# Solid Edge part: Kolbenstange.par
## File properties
Username: bmolnar
Dokumentum tartalom típus: 0
Author: bmolnar
Last saved by: bmolnar
Revision: 83
Sűrűség: 0,000 kg/m^3
Pontosság: 0,990
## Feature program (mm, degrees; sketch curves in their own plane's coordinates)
base feature "unnamed BaseFeature 1"
sketch for "unnamed Protrusion 1" plane through (0, 0, -17.4) normal (0, 0, -1) x-axis (0, 1, 0)
  circle centre (0, 0) radius 20
extrude "unnamed Protrusion 1" add finite 17.45 along +normal
sketch for "Kihúzás_2" #1 plane through (0, 0, -17.4) normal (0, 0, -1) x-axis (0, 1, 0)
  circle centre (0, 0) radius 6
sketch for "Kihúzás_2" #2 plane through (0, 0, -17.4) normal (0, 0, -1) x-axis (0, 1, 0)
  circle centre (0, 0) radius 20
extrude "Kihúzás_2" add finite 12.55 along -normal
sketch for "Furat_1" plane through (0, 0, 49.9) normal (0, 0, 1) x-axis (0, -1, 0)
  hole centre (0, 0) bore radius 2.4585
hole "Furat_1" nominal diameter 6 finite  ThreadDepth = 12.5 mm; VBottomAngle = 118 deg
chamfer "Letörés_1" setback 0.5  SetBackValue2 = 45 deg
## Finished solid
Body 1: solid body, 17 faces, 23 edges, 8 vertices.
  Faces by surface: plane 7, cylinder 5, cone 3, torus 2
  Edges by curve: circle 13, line 6, curve on surface 2, ellipse 2
Bounding box of the edges (mm; curved faces can reach further): 40.000 x 40.000 x 87.250, from (-20, -20, -34.85) to (20, 20, 52.4).
Cylindrical faces by radius (mm): R2.4585 x2, R3.125 x1, R6 x1, R20 x1
Conical faces (half-angle, radius in mm at the cone's reference point): 45 deg R2.9585 x1, 45 deg R3.225 x1, 59 deg R2.4585 x1
Toroidal faces (ring radius, tube radius in mm): R2.925 r0.2 x1, R4.7 r1.3 x1
Planar faces by outward normal: +x 1, +z 2, -x 1, -z 1, oblique 2
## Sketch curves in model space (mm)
circle centre (0, 0, -17.4) radius 6
circle centre (0, 0, -17.4) radius 20
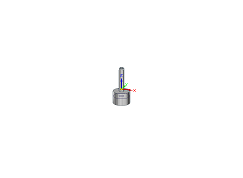
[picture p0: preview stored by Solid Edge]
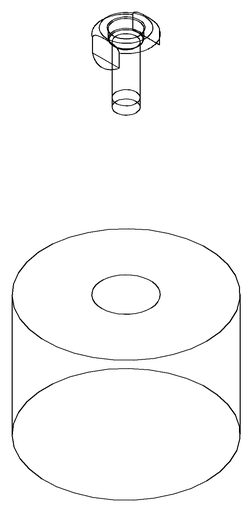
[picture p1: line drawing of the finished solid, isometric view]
